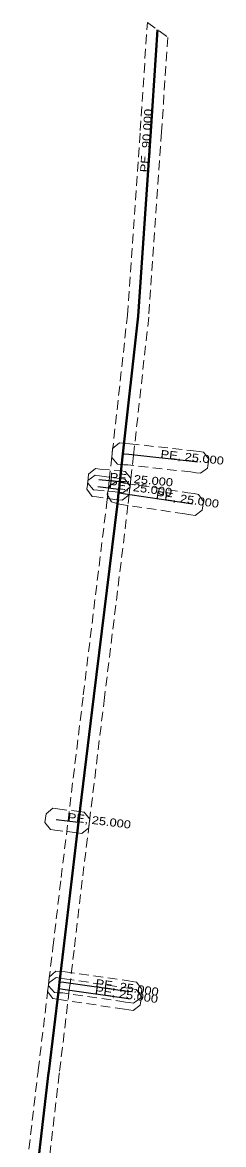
# Model space of a CAD drawing. Extents: x -640775 to -624586, y -1148563 to -1138811.
# Drawn here: x -625518.7 to -625499.9, y -1147527.3 to -1147422.1 of the extents above; entities that cross this region are included whole.
import ezdxf

# ---------------------------------------------------------------- set-up
doc = ezdxf.new("R2010")
doc.units = 0
doc.header["$LTSCALE"] = 0.3
doc.linetypes.add('MEDIUM_DASHED', pattern=[4.5, 3, -1.5])
doc.layers.add('1', color=7, linetype='MEDIUM_DASHED', lineweight=13)
doc.layers.add('24', color=7, linetype='Continuous', lineweight=40)
doc.layers.add('30', color=7, linetype='Continuous')

msp = doc.modelspace()

# ---------------------------------------------------------------- linework, layer by layer
at = {"layer": '1'}
msp.add_lwpolyline([(-625518.272, -1147529.047), (-625517.257, -1147520.432), (-625517.243, -1147520.312), (-625516.312, -1147512.557), (-625516.238, -1147511.935), (-625515.863, -1147508.812), (-625515.093, -1147502.261), (-625514.448, -1147496.953), (-625513.013, -1147485.139), (-625510.813, -1147467.124), (-625510.699, -1147466.09), (-625510.662, -1147465.755), (-625510.584, -1147465.044), (-625510.298, -1147462.447), (-625508.876, -1147449.561), (-625507.678, -1147432.243), (-625507.01, -1147422.126), (-625505.098, -1147423.523), (-625505.682, -1147432.377), (-625506.884, -1147449.739), (-625508.31, -1147462.667), (-625508.596, -1147465.262), (-625508.674, -1147465.973), (-625508.711, -1147466.31), (-625508.827, -1147467.356), (-625511.027, -1147485.381), (-625512.462, -1147497.195), (-625513.107, -1147502.499), (-625513.877, -1147509.048), (-625514.252, -1147512.173), (-625514.326, -1147512.795), (-625515.257, -1147520.548), (-625515.271, -1147520.666), (-625516.288, -1147529.293)], dxfattribs=at)
for points in [[(-625501.378, -1147463.881), (-625502.041, -1147464.378), (-625502.451, -1147464.32), (-625502.926, -1147464.252), (-625508.854, -1147463.596), (-625509.219, -1147463.567), (-625509.383, -1147463.554), (-625509.796, -1147463.521), (-625510.334, -1147462.891), (-625510.301, -1147462.478), (-625510.268, -1147462.065), (-625509.638, -1147461.527), (-625509.225, -1147461.56), (-625509.061, -1147461.573), (-625508.666, -1147461.604), (-625502.674, -1147462.268), (-625502.169, -1147462.34), (-625501.759, -1147462.398), (-625501.262, -1147463.061), (-625501.32, -1147463.471)], [(-625512.517, -1147464.465), (-625511.88, -1147463.936), (-625511.468, -1147463.974), (-625509.524, -1147464.155), (-625509.49, -1147464.158), (-625509.078, -1147464.199), (-625508.554, -1147464.84), (-625508.595, -1147465.253), (-625508.636, -1147465.665), (-625509.277, -1147466.189), (-625509.69, -1147466.148), (-625509.716, -1147466.145), (-625511.652, -1147465.966), (-625512.065, -1147465.927), (-625512.594, -1147465.29), (-625512.556, -1147464.878)], [(-625512.576, -1147465.057), (-625511.917, -1147464.554), (-625511.507, -1147464.609), (-625509.572, -1147464.868), (-625509.544, -1147464.872), (-625509.133, -1147464.923), (-625508.625, -1147465.577), (-625508.676, -1147465.988), (-625508.727, -1147466.399), (-625509.381, -1147466.907), (-625509.792, -1147466.856), (-625509.828, -1147466.852), (-625511.773, -1147466.591), (-625512.183, -1147466.536), (-625512.686, -1147465.877), (-625512.631, -1147465.467)], [(-625501.867, -1147467.835), (-625502.537, -1147468.323), (-625502.946, -1147468.258), (-625503.511, -1147468.169), (-625509.478, -1147467.292), (-625509.841, -1147467.198), (-625509.957, -1147467.168), (-625510.358, -1147467.063), (-625510.777, -1147466.349), (-625510.673, -1147465.948), (-625510.568, -1147465.547), (-625509.854, -1147465.128), (-625509.453, -1147465.232), (-625509.339, -1147465.262), (-625509.082, -1147465.328), (-625503.209, -1147466.191), (-625502.634, -1147466.282), (-625502.225, -1147466.347), (-625501.737, -1147467.017), (-625501.802, -1147467.426)], [(-625516.511, -1147496.275), (-625515.857, -1147495.767), (-625515.446, -1147495.818), (-625513.371, -1147496.077), (-625513.341, -1147496.08), (-625512.93, -1147496.127), (-625512.414, -1147496.776), (-625512.461, -1147497.188), (-625512.508, -1147497.599), (-625513.157, -1147498.115), (-625513.569, -1147498.068), (-625513.609, -1147498.063), (-625515.694, -1147497.802), (-625516.105, -1147497.751), (-625516.613, -1147497.097), (-625516.562, -1147496.686)], [(-625507.638, -1147513.531), (-625508.301, -1147514.028), (-625508.711, -1147513.97), (-625509.062, -1147513.92), (-625514.933, -1147513.076), (-625515.213, -1147513.058), (-625515.308, -1147513.052), (-625515.721, -1147513.026), (-625516.269, -1147512.404), (-625516.243, -1147511.991), (-625516.217, -1147511.578), (-625515.595, -1147511.03), (-625515.182, -1147511.056), (-625515.087, -1147511.062), (-625514.727, -1147511.084), (-625508.778, -1147511.94), (-625508.429, -1147511.99), (-625508.019, -1147512.048), (-625507.522, -1147512.711), (-625507.58, -1147513.121)], [(-625507.685, -1147514.221), (-625508.353, -1147514.711), (-625508.762, -1147514.648), (-625509.148, -1147514.589), (-625515.072, -1147513.728), (-625515.387, -1147513.678), (-625515.474, -1147513.664), (-625515.883, -1147513.599), (-625516.371, -1147512.93), (-625516.307, -1147512.521), (-625516.242, -1147512.112), (-625515.573, -1147511.624), (-625515.164, -1147511.688), (-625515.073, -1147511.702), (-625514.768, -1147511.752), (-625508.852, -1147512.611), (-625508.458, -1147512.672), (-625508.049, -1147512.735), (-625507.559, -1147513.403), (-625507.622, -1147513.812)]]:
    msp.add_lwpolyline(points, close=True, dxfattribs=at)
at = {"layer": '24'}
for points in [[(-625506.054, -1147422.825), (-625506.68, -1147432.31), (-625507.88, -1147449.65), (-625509.304, -1147462.557), (-625509.59, -1147465.153), (-625509.668, -1147465.864), (-625509.705, -1147466.2)], [(-625509.705, -1147466.2), (-625509.82, -1147467.24), (-625512.02, -1147485.26), (-625513.455, -1147497.074)], [(-625513.455, -1147497.074), (-625514.1, -1147502.38), (-625514.87, -1147508.93), (-625515.245, -1147512.054), (-625515.319, -1147512.676)], [(-625515.319, -1147512.676), (-625516.25, -1147520.43), (-625516.264, -1147520.549)], [(-625516.264, -1147520.549), (-625517.28, -1147529.17), (-625518.64, -1147539.67), (-625518.72, -1147540.34)]]:
    msp.add_lwpolyline(points, dxfattribs=at)
at = {"layer": '24', "lineweight": 25}
for points in [[(-625502.31, -1147463.33), (-625502.8, -1147463.26), (-625508.76, -1147462.6), (-625509.14, -1147462.57), (-625509.304, -1147462.557)], [(-625511.56, -1147464.97), (-625509.62, -1147465.15), (-625509.59, -1147465.153)], [(-625511.64, -1147465.6), (-625509.7, -1147465.86), (-625509.668, -1147465.864)], [(-625502.79, -1147467.27), (-625503.36, -1147467.18), (-625509.28, -1147466.31), (-625509.59, -1147466.23), (-625509.705, -1147466.2)], [(-625515.57, -1147496.81), (-625513.49, -1147497.07), (-625513.455, -1147497.074)], [(-625508.57, -1147512.98), (-625508.92, -1147512.93), (-625514.83, -1147512.08), (-625515.15, -1147512.06), (-625515.245, -1147512.054)], [(-625508.61, -1147513.66), (-625509, -1147513.6), (-625514.92, -1147512.74), (-625515.23, -1147512.69), (-625515.319, -1147512.676)]]:
    msp.add_lwpolyline(points, dxfattribs=at)

# ---------------------------------------------------------------- texts
at = {"layer": '30', "width": 1.2}
for s, rotation, p in [('PE, 90.000', 86.041, (-625506.949, -1147436.194)), ('PE, 25.000', 353.681, (-625505.805, -1147462.927)), ('PE, 25.000', 352.367, (-625510.654, -1147465.732)), ('PE, 25.000', 354.699, (-625510.575, -1147465.061)), ('PE, 25.000', 351.64, (-625506.252, -1147466.755)), ('PE, 25.000', 352.875, (-625514.513, -1147496.942)), ('PE, 25.000', 351.734, (-625511.965, -1147513.169)), ('PE, 25.000', 351.816, (-625511.906, -1147512.501))]:
    msp.add_text(s, height=0.75, rotation=rotation, dxfattribs=at).set_placement(p)

doc.saveas('drawing.dxf')
